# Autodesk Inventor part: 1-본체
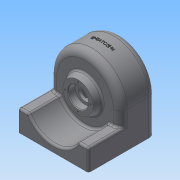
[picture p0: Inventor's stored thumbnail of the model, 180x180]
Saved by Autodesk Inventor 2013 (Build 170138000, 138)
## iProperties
Created: 2015-02
Part Number: 1-본체
Material: 일반
Document SubType Name: Modeling
Designer: Administrator
Density: 1 g/cm^3
Author: Administrator
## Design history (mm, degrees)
sketch "스케치1"
  geometry: L1 (-50, -50)-(50, -50); L2 (50, -50)-(50, 0); L3 (-50, 0)-(-50, -50); A1 r 50 centre (0, 0) between (50, 0) and (-50, 0); 1 further point
  constraints: 6 end point, 2 perpendicular, 2 point on circle, 1 centre point, 1 coincident, 1 horizontal, 1 parallel, 1 tangent
  dimensions: "d0" = 50 radius of A1; "d2" = 50 distance from line of L1 A1.centre
extrude "돌출1" new body sketch "스케치1" distance "d3" = 50; taper "d4" = 0 deg
fillet "모깎기1" dims "d5" = 10
feature "쉘1" dims "d6" = 4
node "작업 평면1"
sketch "스케치2"
  geometry: L1 (-50, 0)-(-50, -50) reference; L2 (50, -50)-(50, 0) reference; L3 (-40, -50)-(-50, -50) reference; L4 (-40, -50)-(40, -50) reference; L5 (50, -50)-(40, -50) reference; L6 (-40, -20)-(-34.641, -20); L7 (50, -20)-(34.641, -20); L8 (-34.641, -20)-(-50, -20); A1 r 40 centre (0, 0) between (-34.641, -20) and (34.641, -20); 1 further point
  constraints: 6 end point, 3 point on line, 2 point on circle, 1 centre point, 1 coincident, 1 collinear
  dimensions: "d8" = 40 radius of A1; "d11" = 30 distance between parallel lines of L4 L7; "d12" = 90 distance from line of L6.start L2
extrude "돌출2" join sketch "스케치2" stored distance "d13" = 50; taper "d14" = 0 deg
sketch "스케치3"
  geometry: C1 r 25 at (0, 0); A1 r 40 centre (0, 0) between (-34.641, -20) and (34.641, -20) reference
  constraints: 1 centre point, 1 coincident
  dimensions: "d15" = 50 diameter of C1
extrude "돌출3" join sketch "스케치3" distance "d17" = 10; taper "d18" = -20 deg
sketch "스케치4"
  geometry: C1 r 20 at (0, 0); A1 r 40 centre (0, 0) between (40, 0) and (-40, 0) reference
  constraints: 1 centre point, 1 coincident
  dimensions: "d19" = 40 diameter of C1
extrude "돌출4" join sketch "스케치4" distance "d21" = 9; taper "d22" = 0 deg
hole "구멍1" diameter "d25" = 20; stored, may be unused: countersink angle "d29" = 90 deg, drill point angle "d31" = 118 deg; dims "d23" = 10, "d24" = 10, "d26" = 6, "d27" = 28, "d28" = 10, "d30" = 8
hole "구멍2" diameter "d34" = 20; stored, may be unused: countersink angle "d38" = 90 deg, drill point angle "d40" = 0 deg; dims "d32" = 10, "d33" = 10, "d35" = 6, "d36" = 28, "d37" = 8, "d39" = 10
sketch "스케치6"
  geometry: C1 r 14 at (0, 0) reference; C2 r 21.36 at (0, 0) reference; A1 r 18 centre (0, 0) between (0, 18) and (-18, 0); 2 further points
  constraints: 4 point on circle, 2 horizontal alignment, 2 vertical alignment, 1 centre point, 1 coincident
  dimensions: "d41" = 36 diameter of A1
hole "구멍3" sketch "스케치6" at (0, 18), (-18, 0), (18, 0), (0, -18) diameter "d43" = 2.459; stored, may be unused: countersink angle "d47" = 90 deg, drill point angle "d49" = 118 deg; dims "d44" = 6, "d45" = 28, "d46" = 8, "d48" = 9
sketch "스케치7"
  geometry: L1 (-10, 95)-(90, 95) reference; L2 (81.75, 53)-(-1.75, 53); L3 (-1.75, 53)-(-1.75, 86); L4 (-1.75, 86)-(81.75, 86); L5 (81.75, 86)-(81.75, 53); L6 (81.75, 53)-(-1.75, 86); L7 (-1.75, 53)-(81.75, 86); 8 further points
  constraints: 12 end point, 4 coincident, 4 midpoint, 2 parallel, 1 horizontal, 1 perpendicular, 1 vertical alignment
  dimensions: "d50" = 9 distance between parallel lines of L4 L1; "d51" = 33 distance of L4.end L2.start; "d52" = 83.5 distance of L3.end L4.end
hole "구멍4" sketch "스케치7" at (-1.75, 86), (81.75, 86), (81.75, 53), (-1.75, 53) diameter "d53" = 5.134; stored, may be unused: countersink angle "d57" = 90 deg, drill point angle "d59" = 118 deg; dims "d54" = 10, "d55" = 28, "d56" = 8, "d58" = 13
fillet "모깎기2" dims "d60" = 0.3, "d61" = 3
fillet "모깎기3" dims "d62" = 3
chamfer "모따기1" distance "d63" = 1; stored, may be unused: second distance "d64" = 2, angle "d65" = 45 deg
node "작업 평면2"
sketch "스케치8"
  geometry: L1 (-21.36, 60)-(21.36, 60) reference; L2 (40, 0)-(-40, 0) reference; 3 further points
  constraints: 1 midpoint, 1 vertical alignment, 1 other
  dimensions: "d66" = 25 distance from line of point (0, 25) L2
feature "엠보싱1" sketch "스케치8" dims "d0" = 50, "d2" = 50, "d67" = 0.5, "d68" = 0
node "솔리드1"
other parameters: "d7" = -95
